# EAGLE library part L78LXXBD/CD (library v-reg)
VOLTAGE REGULATOR
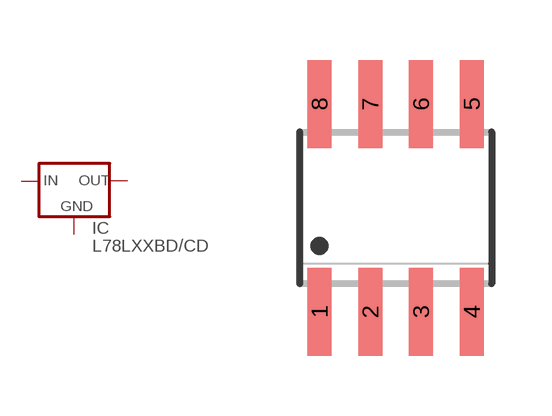
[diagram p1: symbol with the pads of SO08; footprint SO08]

Designator prefix IC

## L78LXXBD/CD  [SO08]
1  OUT  pas
2  GND1  in
3  GND2  in
6  GND3  in
7  GND4  in
8  IN  in

## Footprint SO08 (pad centres in mm)
SMALL OUTLINE INTEGRATED CIRCUIT body 3.9 mm/JEDEC MS-012AA
smd 0.6 x 2.2: 1 -1.905,-2.6; 2 -0.635,-2.6; 3 0.635,-2.6; 4 1.905,-2.6; 5 1.905,2.6; 6 0.635,2.6; 7 -0.635,2.6; 8 -1.905,2.6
